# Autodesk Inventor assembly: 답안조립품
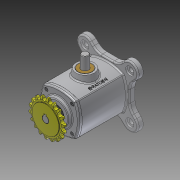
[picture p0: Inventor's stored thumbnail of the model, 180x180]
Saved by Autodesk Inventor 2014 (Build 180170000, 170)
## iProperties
Created: 2016-05
Part Number: 답안조립품
Document SubType Name: Assembly
Designer: J.H.Beak
Author: J.H.Beak
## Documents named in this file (11)
- C:\Users\Administrator\Desktop\460507V1026\답안조립품.iam
- C:\Users\Administrator\Desktop\460507V1026\본체.ipt
- C:\Users\Administrator\Desktop\460507V1026\M4x0.7x12.ipt
- C:\Users\Administrator\Desktop\460507V1026\베어링-6203.ipt
- C:\Users\Administrator\Desktop\460507V1026\부시.ipt
- C:\Users\Administrator\Desktop\460507V1026\스프로킷.ipt
- C:\Users\Administrator\Desktop\460507V1026\슬라이더.ipt
- C:\Users\Administrator\Desktop\460507V1026\오일실.ipt
- C:\Users\Administrator\Desktop\460507V1026\커버.ipt
- C:\Users\Administrator\Desktop\460507V1026\키5x5.ipt
- C:\Users\Administrator\Desktop\460507V1026\편심축.ipt
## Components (8 placed, 1 different names)
1. M4x0.7x12:2
2. M4x0.7x12:3
3. M4x0.7x12:4
4. M4x0.7x12:5
5. M4x0.7x12:1
6. M4x0.7x12:6
7. M4x0.7x12:7
8. M4x0.7x12:8
